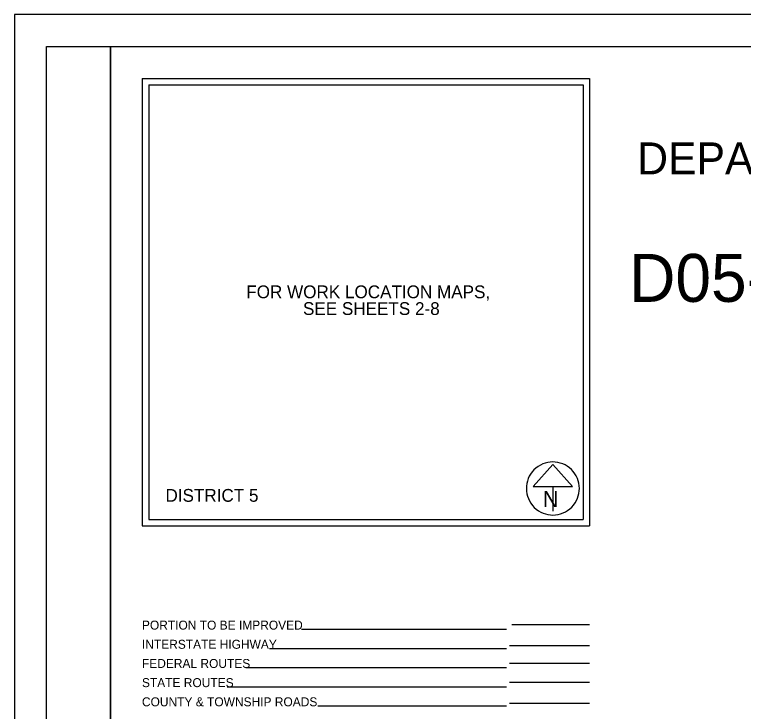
# Model space of a CAD drawing. Extents: x 0 to 34, y 0 to 22.
# Drawn here: x 0 to 11.41, y 11.1 to 22 of the extents above; entities that cross this region are included whole.
import ezdxf

# ---------------------------------------------------------------- set-up
doc = ezdxf.new("R2010")
doc.units = 0
for name, color, linetype in [('SH_Border', 7, 'Continuous'), ('SH_Cut_Line', 7, 'Continuous'), ('SH_Data', 7, 'Continuous'), ('SH_Text', 7, 'Continuous')]:
    doc.layers.add(name, color=color, linetype=linetype)

msp = doc.modelspace()

# ---------------------------------------------------------------- linework, layer by layer
at = {"layer": 'SH_Border'}
for points in [[(0.5, 21.5), (1.5, 21.5), (1.5, 0.5), (0.5, 0.5)], [(1.5, 21.5), (33.5, 21.5), (33.5, 0.5), (1.5, 0.5)]]:
    msp.add_lwpolyline(points, close=True, dxfattribs=at)
at = {"layer": 'SH_Cut_Line'}
msp.add_lwpolyline([(0, 0), (34, 0), (34, 22), (0, 22)], close=True, dxfattribs=at)
at = {"layer": 'SH_Data'}
for p, q in [((2, 21), (9, 21)), ((2, 21), (2, 14)), ((9, 21), (9, 14)), ((2.1, 20.9), (2.1, 14.1)), ((2.1, 20.9), (8.9, 20.9)), ((8.9, 20.9), (8.9, 14.1)), ((8.427, 14.958), (8.12, 14.617)), ((8.735, 14.617), (8.427, 14.958)), ((8.12, 14.617), (8.735, 14.617)), ((8.427, 14.617), (8.427, 14.23)), ((8.427, 14.585), (8.427, 14.585)), ((8.427, 14.585), (8.427, 14.585)), ((2.1, 14.1), (8.9, 14.1)), ((2.1, 14.1), (2.1, 14.1)), ((2, 14), (9, 14)), ((7.783, 12.455), (9, 12.455)), ((7.7, 12.377), (4.494, 12.377)), ((9, 12.121), (7.75, 12.121)), ((7.7, 12.077), (3.99, 12.077)), ((7.7, 11.777), (3.619, 11.777)), ((9, 11.849), (7.75, 11.849)), ((9, 11.549), (7.75, 11.549)), ((7.7, 11.477), (3.329, 11.477)), ((9, 11.222), (7.75, 11.222)), ((7.7, 11.177), (4.745, 11.177))]:
    msp.add_line(p, q, dxfattribs=at)
msp.add_arc((8.427, 14.585), 0.415, 129.7798, 129.7633, dxfattribs=at)

# ---------------------------------------------------------------- texts
msp.add_text('N', height=0.25, dxfattribs=at).set_placement((8.272, 14.293))
at = {"layer": 'SH_Text'}
for s, height, p in [('DEPARTMENT OF TRANSPORTATION', 0.5, (9.747, 19.5)), ('D05-GR-FY2025 (Ding N Dent)', 0.75, (9.621, 17.505)), ('FOR WORK LOCATION MAPS,', 0.2, (3.627, 17.562)), ('SEE SHEETS 2-8', 0.2, (4.515, 17.3)), ('DISTRICT 5', 0.2, (2.362, 14.377)), ('PORTION TO BE IMPROVED', 0.14, (1.994, 12.377)), ('INTERSTATE HIGHWAY', 0.14, (1.994, 12.077)), ('FEDERAL ROUTES', 0.14, (1.994, 11.777)), ('STATE ROUTES', 0.14, (1.994, 11.477)), ('COUNTY & TOWNSHIP ROADS', 0.14, (1.994, 11.177))]:
    msp.add_text(s, height=height, dxfattribs=at).set_placement(p)

doc.saveas('drawing.dxf')
